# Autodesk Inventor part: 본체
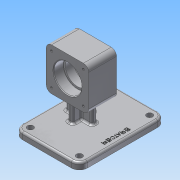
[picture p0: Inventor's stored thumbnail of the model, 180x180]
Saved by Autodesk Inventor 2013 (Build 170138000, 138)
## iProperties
Created: 2020-11
Part Number: 본체
Material: 알루미늄 6061
Document SubType Name: Modeling
Designer: Administrator
Density: 2.71 g/cm^3
Mass: 685.745 g
Surface Area: 542.794 cm^2
Volume: 253.042 cm^3
Author: Administrator
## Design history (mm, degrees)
sketch "스케치2"
  geometry: L1 (32, -32)-(-32, -32); L2 (-32, -32)-(-32, 32); L3 (-32, 32)-(32, 32); L4 (32, 32)-(32, -32); L5 (32, -32)-(-32, 32); L6 (-32, -32)-(32, 32); 1 further point
  constraints: 12 end point, 2 midpoint, 2 parallel, 1 horizontal, 1 perpendicular
  dimensions: "d0" = 64 distance of L2.end L3.end; "d2" = 64 distance of L3.end L1.start
extrude "돌출1" new body sketch "스케치2" distance "d3" = 42; taper "d4" = 0 deg
sketch "스케치3"
  geometry: C1 r 21 at (0, 0); 1 further point
  constraints: 1 centre point, 1 coincident
  dimensions: "d5" = 42 diameter of C1
extrude "돌출2" cut sketch "스케치3" distance "d7" = 15; taper "d8" = 0 deg
sketch "스케치4"
  geometry: C1 r 21 at (0, 0); 1 further point
  constraints: 1 centre point, 1 coincident
  dimensions: "d9" = 42 diameter of C1
extrude "돌출3" cut sketch "스케치4" distance "d11" = 15; taper "d12" = 0 deg
sketch "스케치5"
  geometry: C1 r 18 at (0, 0); 1 further point
  constraints: 1 centre point, 1 coincident
  dimensions: "d13" = 36 diameter of C1
extrude "돌출4" cut sketch "스케치5" distance "d15" = 15; taper "d16" = 0 deg
fillet "모깎기1" dims "d17" = 0.3
fillet "모깎기2" dims "d18" = 8
sketch "스케치6"
  geometry: 5 further points
  dimensions: "d19" = 48 distance of point (24, 24) point (-24, 24); "d21" = 48 distance of point (24, -24) point (-24, -24); "d22" = 48 distance of point (-24, -24) point (-24, 24); "d23" = 48 distance of point (24, -24) point (24, 24); "d24" = 24 horizontal distance of point (24, 24) point (0, 0); "d25" = 24 horizontal distance of point (24, -24) point (0, 0); "d26" = 24 horizontal distance of point (-24, -24) point (0, 0); "d27" = 24 horizontal distance of point (24, -24) point (0, 0)
hole "구멍1" sketch "스케치6" at (-24, 24), (24, 24), (24, -24), (-24, -24) diameter "d28" = 3.242; stored, may be unused: countersink angle "d32" = 90 deg, drill point angle "d34" = 118 deg; dims "d29" = 8, "d30" = 4, "d31" = 2, "d33" = 10
sketch "스케치7"
  geometry: 5 further points
  dimensions: "d35" = 48 distance of point (24, 24) point (-24, 24); "d37" = 48 distance of point (24, -24) point (-24, -24); "d38" = 48 distance of point (-24, -24) point (-24, 24); "d39" = 48 distance of point (24, -24) point (24, 24); "d40" = 24 horizontal distance of point (-24, 24) point (0, 0); "d41" = 24 horizontal distance of point (-24, -24) point (0, 0); "d42" = 24 horizontal distance of point (-24, -24) point (0, 0); "d43" = 24 horizontal distance of point (24, 24) point (0, 0)
hole "구멍2" sketch "스케치7" at (24, -24), (-24, -24), (24, 24), (-24, 24) diameter "d44" = 3.242; stored, may be unused: countersink angle "d48" = 90 deg, drill point angle "d50" = 118 deg; dims "d45" = 8, "d46" = 4, "d47" = 2, "d49" = 10
chamfer "모따기1" distance "d51" = 1; stored, may be unused: second distance "d52" = 2, angle "d53" = 45 deg
node "작업 평면1"
sketch "스케치8"
  geometry: L1 (-36, -44)-(62, -44); L2 (62, -44)-(62, 86); L3 (62, 86)-(-36, 86); L4 (-36, 86)-(-36, -44); L5 (-36, -44)-(62, 86); L6 (62, -44)-(-36, 86); L7 (-24, 0)-(24, 0) reference; 2 further points
  constraints: 12 end point, 2 midpoint, 2 parallel, 1 horizontal, 1 perpendicular
  dimensions: "d55" = 130 distance of L1.end L2.end; "d57" = 98 distance of L1.start L1.end; "d58" = 62 distance from line of point (0, 0) L2; "d60" = 44 distance between parallel lines of L1 L7
extrude "돌출5" join sketch "스케치8" distance "d61" = 10; taper "d62" = 0 deg
sketch "스케치9"
  geometry: L1 (20, 25)-(20, 17); L2 (20, 17)-(4, 17); L3 (4, 17)-(4, 4); L4 (4, 4)-(-4, 4); L5 (-4, 4)-(-4, 17); L6 (-4, 17)-(-20, 17); L7 (-20, 17)-(-20, 25); L8 (-20, 25)-(-4, 25); L9 (-4, 25)-(-4, 38); L10 (-4, 38)-(4, 38); L11 (4, 38)-(4, 25); L12 (4, 25)-(20, 25); L13 (20, 21)-(-20, 21); L14 (0, 38)-(0, 4); L15 (24, 42)-(-24, 42) reference; L16 (-32, 0)-(-32, 42) reference; 1 further point
  constraints: 28 end point, 7 parallel, 4 midpoint, 2 collinear, 2 perpendicular, 1 vertical
  dimensions: "d74" = 17 distance between parallel lines of L4 L13; "d76" = 17 distance from line of L14.start L13; "d77" = 20 distance between parallel lines of L7 L14; "d78" = 20 distance between parallel lines of L1 L14; "d79" = 8 distance of L3.end L4.end; "d80" = 8 distance of L1.start L1.end; "d81" = 8 distance of L9.end L10.end; "d82" = 8 distance of L6.end L7.end; "d83" = 4 distance between parallel lines of L15 L10; "d84" = 12 distance between parallel lines of L16 L7
extrude "돌출6" join sketch "스케치9" stored distance "d85" = 10; taper "d86" = 0 deg
fillet "모깎기3" dims "d87" = 3
fillet "모깎기4" dims "d88" = 3
fillet "모깎기5" dims "d89" = 3
sketch "스케치11"
  geometry: L1 (-36, -44)-(62, -44) reference; L2 (62, -44)-(62, 86) reference; 2 further points
  constraints: 1 other
  dimensions: "d90" = 65 distance from line of point (52, 21) L1; "d91" = 10 distance from line of point (52, 21) L2
extrude "돌출7" join sketch "스케치11" distance "d92" = 0.5; taper "d93" = 0 deg
fillet "모깎기6" dims "d94" = 12
fillet "모깎기7" dims "d95" = 3
sketch "스케치12"
  geometry: C1 r 4.5 at (-24, 74); C2 r 4.5 at (50, 74); C3 r 4.5 at (-24, -32); C4 r 4.5 at (50, -32); C5 r 12 at (-24, 74); C6 r 12 at (50, 74); C7 r 12 at (-24, -32); C8 r 12 at (50, -32); A1 r 12 centre (-24, 74) between (-24, 86) and (-36, 74) reference; A2 r 12 centre (50, 74) between (62, 74) and (50, 86) reference; A3 r 12 centre (50, -32) between (50, -44) and (62, -32) reference; A4 r 12 centre (-24, -32) between (-36, -32) and (-24, -44) reference; 1 further point
  constraints: 8 centre point, 4 coincident, 4 concentric, 3 equal radius
  dimensions: "d96" = 9 diameter of C1; "d98" = 24 diameter of C5; "d99" = 24 diameter of C6; "d100" = 24 diameter of C7; "d101" = 24 diameter of C8
extrude "돌출8" cut sketch "스케치12" stored distance "d102" = 0.5; taper "d103" = 0 deg
node "솔리드1"
